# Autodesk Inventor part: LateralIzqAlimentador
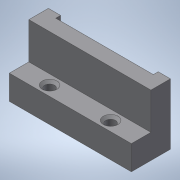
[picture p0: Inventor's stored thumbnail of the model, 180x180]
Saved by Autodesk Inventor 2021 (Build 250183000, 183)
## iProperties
Created: 2021-02
Part Number: LateralIzqAlimentador
Material: Genérico
Document SubType Name: Modeling
Designer: ATOUZA
Density: 1 g/cm^3
Appearance: Valor por defecto
Author: ATOUZA
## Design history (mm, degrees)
node "Plano de trabajo1"
sketch "Boceto1"
  geometry: L1 (-20, 18)-(20, 18) reference; L2 (20, 20)-(20, 18) reference; L3 (-20, 20)-(20, 20) reference; L4 (-20, 18)-(-20, 20) reference; L5 (20, 20)-(-20, 20); L6 (25, 26)-(-25, 26); L7 (-25, 26)-(-25, 18); L8 (-25, 18)-(-20, 18); L9 (-20, 18)-(-20, 20); L10 (25, 26)-(25, 18); L11 (25, 18)-(20, 18); L12 (20, 18)-(20, 20); L13 (25, 26)-(-25, 26); 1 further point
  constraints: 18 end point, 3 horizontal, 3 parallel, 2 point on line, 1 perpendicular
  dimensions: "d1" = 5 distance of L8.end L7.end; "d2" = 5 distance of L10.end L11.end; "d3" = 8 distance of L6.start L10.end; "d4" = 50 distance of L6.start L6.end
extrude "Extrusión2" new body sketch "Boceto1" distance "d17" = 25; taper "d18" = 0 deg
sketch "Boceto4"
  geometry: L1 (-25, 26)-(25, 26) reference; L2 (25, 26)-(-25, 26); L3 (-25, 26)-(-25, 34); L4 (-25, 34)-(25, 34); L5 (25, 34)-(25, 26); L6 (-20, 18)-(-20, 20) reference; L7 (-20, 20)-(20, 20); L8 (20, 20)-(20, -20); L9 (20, -20)-(-20, -20); L10 (-20, -20)-(-20, 20); L11 (0, 0)-(0, 30); L12 (0, 30)-(-25, 30); L13 (0, 30)-(25, 30); C1 r 2 at (-12.5, 30); C2 r 2 at (12.5, 30); 1 further point
  constraints: 22 end point, 4 midpoint, 4 parallel, 2 centre point, 2 horizontal, 2 perpendicular, 1 vertical
  dimensions: "d19" = 8 distance of L2.end L3.end; "d22" = 40 distance of L8.end L9.end; "d23" = 40 distance of L7.end L8.end; "d26" = 30 distance of L11.start L11.end; "d27" = 4 diameter of C1; "d28" = 4 diameter of C2
extrude "Extrusión3" join sketch "Boceto4" distance "d20" = 10; taper "d21" = 0 deg
sketch "Boceto5"
  geometry: L1 (-25, -34)-(25, -34) reference; L2 (0, -34)-(0, -26); L3 (-25, -26)-(25, -26) reference; L4 (0, -30)-(-25, -30); L5 (0, -30)-(25, -30); L6 (25, -18)-(25, -34) reference; L7 (4.811, 50.86)-(5.011, 50.86) reference; 3 further points
  constraints: 6 end point, 5 midpoint, 2 horizontal, 1 point on line
  dimensions: "d36" = 12.5 distance from line of L2 point (-12.5, -30)
hole "Agujero2" sketch "Boceto5" at (-12.5, -30), (12.5, -30) diameter "d29" = 4; stored, may be unused: countersink angle "d33" = 90 deg, drill point angle "d35" = 118 deg; dims "d30" = 6, "d31" = 6, "d32" = 2, "d34" = 8
node "Sólido2"
node "Referencia1"
node "Referencia3"
